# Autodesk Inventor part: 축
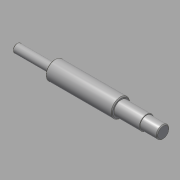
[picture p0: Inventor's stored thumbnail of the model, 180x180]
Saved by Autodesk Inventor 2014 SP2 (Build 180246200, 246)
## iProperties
Created: 2016-05
Part Number: 축
Document SubType Name: Modeling
Designer: mduedu
Density: 7.86 g/cm^3
Material: 강철, 연강
Appearance: 강철
Author: mduedu
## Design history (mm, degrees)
sketch "스케치1"
  geometry: L1 (-42, 11)-(-42, 5); L2 (37, 11)-(37, 8.5); L3 (-87, 0)-(87, 0); L4 (-42, 11)-(37, 11); L5 (37, 11)-(37, 8.5); L6 (-42, 11)-(-42, 5); L7 (-42, 5)-(-87, 5); L8 (-87, 5)-(-87, 0); L9 (37, 8.5)-(67, 8.5); L10 (87, 7.5)-(87, 0); L11 (67, 8.5)-(67, 7.5); L12 (67, 7.5)-(87, 7.5); 1 further point
  constraints: 24 end point, 9 perpendicular, 2 midpoint, 1 horizontal
  dimensions: "d0" = 22 diameter of L4 L3; "d1" = 10 diameter of L7 L3; "d2" = 45 distance between parallel lines of L8 L1; "d3" = 50 distance between parallel lines of L10 L2; "d4" = 15 diameter of L12 L3; "d5" = 20 distance between parallel lines of L10 L11; "d29" = 79 distance of L1.start L2.start; "d37" = 17 diameter of L9 L3
revolve "회전1" stored, may be unused: angle "d6" = 90 deg
chamfer "모따기2" distance "d32" = 1; stored, may be unused: second distance "d33" = 2, angle "d34" = 45 deg
node "작업 평면4"
sketch "스케치4"
  geometry: L1 (-5, 2.5)-(5, 2.5); L2 (5, -2.5)-(-5, -2.5); L3 (-10, -6.5)-(-10, 6.5) reference; A1 r 2.5 centre (5, 0) between (5, -2.5) and (5, 2.5); A2 r 2.5 centre (-5, 0) between (-5, 2.5) and (-5, -2.5); 1 further point
  constraints: 4 end point, 4 point on circle, 4 tangent, 2 centre point, 1 horizontal, 1 horizontal alignment, 1 parallel
  dimensions: "d20" = 5 distance between parallel lines of L2 L1; "d21" = 15 dimension on A1 A2; "d35" = 2.5 distance edge to line of A2 L3
extrude "돌출3" cut sketch "스케치4" distance "d23" = 3; taper "d24" = 0 deg
node "작업 평면5"
sketch "스케치5"
  geometry: L1 (22.5, 1.5)-(10, 1.5); L2 (10, -1.5)-(22.5, -1.5); L3 (22.5, 4)-(22.5, -4) reference; A1 r 1.5 centre (10, 0) between (10, 1.5) and (10, -1.5); 3 further points
  constraints: 4 end point, 2 horizontal alignment, 2 point on circle, 2 point on line, 2 tangent, 1 centre point, 1 coincident, 1 horizontal, 1 midpoint
  dimensions: "d25" = 3 distance between parallel lines of L2 L1; "d36" = 14 dimension on A1 L3
extrude "돌출4" cut sketch "스케치5" distance "d27" = 1.8; taper "d28" = 0 deg
node "솔리드1"
